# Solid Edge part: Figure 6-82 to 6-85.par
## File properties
Author: CADCIM
Template: Normal.par
Last saved by: CADCIM
Revision: 7
Application: Solid Edge
Accuracy: 0.99
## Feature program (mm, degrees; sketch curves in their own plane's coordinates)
sketch for "unnamed Protrusion 1" plane through (0, 0, 0) normal (0, -1, 0) x-axis (1, 0, 0)
  arc centre (0, 0) radius 41.8395 from (-41.8395, 0) to (41.8395, 0) cw
  line (33.5782, 0) -> (41.8395, 0)
  arc centre (0, 0) radius 33.5782 from (-33.5782, 0) to (33.5782, 0) cw
  line (-41.8395, 0) -> (-33.5782, 0)
extrude "unnamed Protrusion 1" add finite 55 symmetric
sketch for "ExtrudedProtrusion_6" plane through (0, 0, 0) normal (0, -1, 0) x-axis (1, 0, 0)
  line (41.8395, 0) -> (76.8395, 0)
  line (76.8395, 0) -> (76.8395, 8.3056)
  line (76.8395, 8.3056) -> (41.0068, 8.3056)
extrude "ExtrudedProtrusion_6" add finite 35 symmetric
fillet "Round_2" radius 17.5
fillet "Round_3" radius 10
sketch for "Hole_2" plane through (58.6295, 0.0111, 8.3056) normal (0, 0, 1) x-axis (0, 1, 0)
  hole centre (-0.0111, -0.71) bore radius 5
hole "Hole_2" diameter 10 through  CounterBoreDepth = 2 mm
mirror "unnamed Mirror 1" of "ExtrudedProtrusion_6", "Round_2", "Round_3", "Hole_2" about plane through (0, 0, 0) normal (1, 0, 0)
extrude "unnamed Protrusion 2" add finite 35 symmetric
fillet "unnamed Round 1"
fillet "unnamed Round 2"
hole "unnamed Hole 1" through
body pattern "unnamed BodyPattern 1"
pattern "unnamed Pattern 1"
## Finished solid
Body 1: solid body, 40 faces, 88 edges, 46 vertices.
  Faces by surface: plane 20, cylinder 14, torus 6
  Edges by curve: circle 46, line 34, intersection 8
Bounding box of the edges (mm; curved faces can reach further): 153.679 x 110.000 x 41.840, from (-76.8395, -82.5, 0) to (76.8395, 27.5, 41.8395).
Cylindrical faces by radius (mm): R5 x4, R8 x4, R17.5 x4, R33.5782 x1, R41.8395 x1
Toroidal faces (ring radius, tube radius in mm): R51.8395 r10 x6
Planar faces by outward normal: +y 5, +z 8, -y 5, -z 2
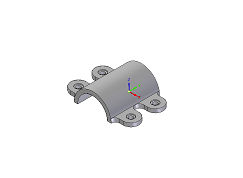
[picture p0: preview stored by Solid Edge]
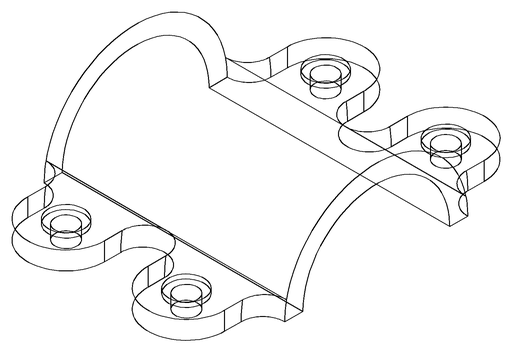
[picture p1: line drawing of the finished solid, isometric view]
